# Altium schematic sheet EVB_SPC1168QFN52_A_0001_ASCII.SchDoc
size A3; 项目编号: SPSZ2023-052501A; 项目名称: 三相PFC-2.2KW压机+700W风机
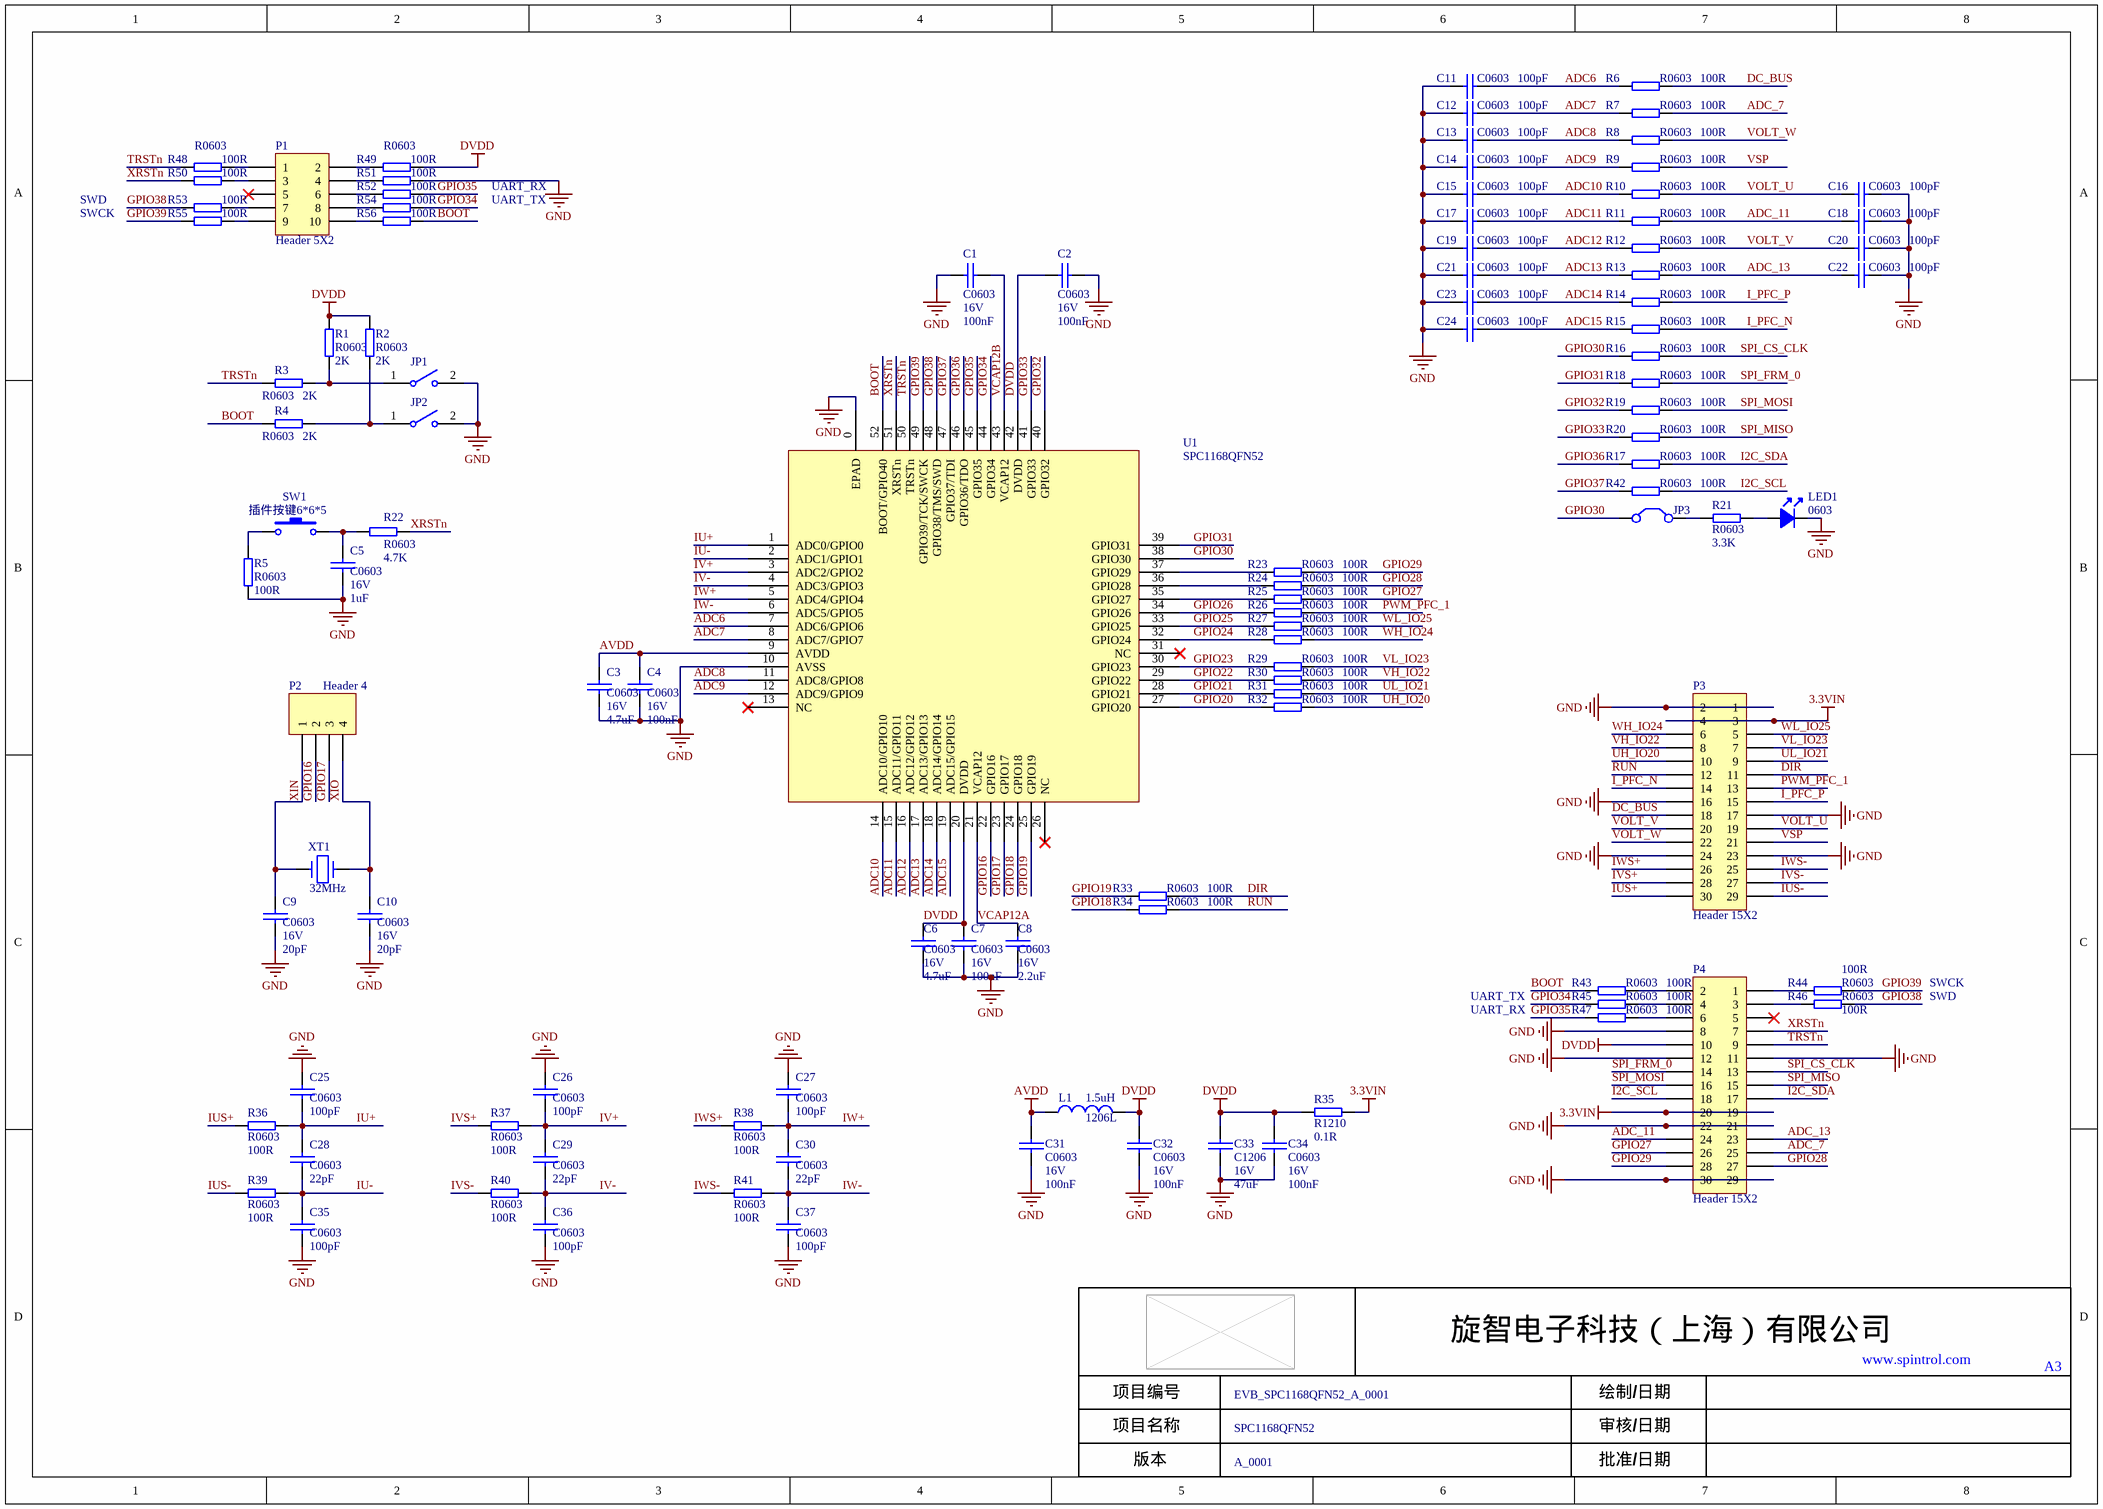
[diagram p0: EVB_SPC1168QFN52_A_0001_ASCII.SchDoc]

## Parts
C1  4.物料简述: C0603  3.物料描述（系统）: 16V  [0603C]  (hidden comment: 100nF)
C2  4.物料简述: C0603  3.物料描述（系统）: 16V  [0603C]  (hidden comment: 100nF)
C3  4.物料简述: C0603  3.物料描述（系统）: 16V  [0603C]  (hidden comment: 4.7uF)
C4  4.物料简述: C0603  3.物料描述（系统）: 16V  [0603C]  (hidden comment: 100nF)
C5  4.物料简述: C0603  3.物料描述（系统）: 16V  [0603C]  (hidden comment: 1uF)
C6  4.物料简述: C0603  3.物料描述（系统）: 16V  [0603C]  (hidden comment: 4.7uF)
C7  4.物料简述: C0603  3.物料描述（系统）: 16V  [0603C]  (hidden comment: 100nF)
C8  4.物料简述: C0603  3.物料描述（系统）: 16V  [0603C]  (hidden comment: 2.2uF)
C9  4.物料简述: C0603  3.物料描述（系统）: 16V  [0603C]  (hidden comment: 20pF)
C10  4.物料简述: C0603  3.物料描述（系统）: 16V  [0603C]  (hidden comment: 20pF)
C11  4.物料简述: C0603  [0603C]  (hidden comment: 100pF)
C12  4.物料简述: C0603  [0603C]  (hidden comment: 100pF)
C13  4.物料简述: C0603  [0603C]  (hidden comment: 100pF)
C14  4.物料简述: C0603  [0603C]  (hidden comment: 100pF)
C15  4.物料简述: C0603  [0603C]  (hidden comment: 100pF)
C16  4.物料简述: C0603  [0603C]  (hidden comment: 100pF)
C17  4.物料简述: C0603  [0603C]  (hidden comment: 100pF)
C18  4.物料简述: C0603  [0603C]  (hidden comment: 100pF)
C19  4.物料简述: C0603  [0603C]  (hidden comment: 100pF)
C20  4.物料简述: C0603  [0603C]  (hidden comment: 100pF)
C21  4.物料简述: C0603  [0603C]  (hidden comment: 100pF)
C22  4.物料简述: C0603  [0603C]  (hidden comment: 100pF)
C23  4.物料简述: C0603  [0603C]  (hidden comment: 100pF)
C24  4.物料简述: C0603  [0603C]  (hidden comment: 100pF)
C25  4.物料简述: C0603  [0603C]  (hidden comment: 100pF)
C26  4.物料简述: C0603  [0603C]  (hidden comment: 100pF)
C27  4.物料简述: C0603  [0603C]  (hidden comment: 100pF)
C28  4.物料简述: C0603  [0603C]  (hidden comment: 22pF)
C29  4.物料简述: C0603  [0603C]  (hidden comment: 22pF)
C30  4.物料简述: C0603  [0603C]  (hidden comment: 22pF)
C31  4.物料简述: C0603  3.物料描述（系统）: 16V  [0603C]  (hidden comment: 100nF)
C32  4.物料简述: C0603  3.物料描述（系统）: 16V  [0603C]  (hidden comment: 100nF)
C33  4.物料简述: C1206  3.物料描述（系统）: 16V  [1206C]  (hidden comment: 47uF)
C34  4.物料简述: C0603  3.物料描述（系统）: 16V  [0603C]  (hidden comment: 100nF)
C35  4.物料简述: C0603  [0603C]  (hidden comment: 100pF)
C36  4.物料简述: C0603  [0603C]  (hidden comment: 100pF)
C37  4.物料简述: C0603  [0603C]  (hidden comment: 100pF)
JP1  DSIC01LH-P  [Switch_3.5*10.4]  (value not drawn)
JP2  DSIC01LH-P  [Switch_3.5*10.4]  (value not drawn)
JP3  Jumper  [HDR1X2]  (value not drawn)
L1  1.5uH  [1206L]
LED1  4.物料简述: 0603  [LED0603]
P1  Header 5X2  [HDR2X5]
P2  Header 4  [HDR1X4]
P3  Header 15X2  [HDR2X15]
P4  Header 15X2  [HDR2X15]
R1  4.物料简述: R0603  [0603R]  (hidden comment: 2K)
R2  4.物料简述: R0603  [0603R]  (hidden comment: 2K)
R3  4.物料简述: R0603  [0603R]  (hidden comment: 2K)
R4  4.物料简述: R0603  [0603R]  (hidden comment: 2K)
R5  4.物料简述: R0603  [0603R]  (hidden comment: 100R)
R6  4.物料简述: R0603  [0603R]  (hidden comment: 100R)
R7  4.物料简述: R0603  [0603R]  (hidden comment: 100R)
R8  4.物料简述: R0603  [0603R]  (hidden comment: 100R)
R9  4.物料简述: R0603  [0603R]  (hidden comment: 100R)
R10  4.物料简述: R0603  [0603R]  (hidden comment: 100R)
R11  4.物料简述: R0603  [0603R]  (hidden comment: 100R)
R12  4.物料简述: R0603  [0603R]  (hidden comment: 100R)
R13  4.物料简述: R0603  [0603R]  (hidden comment: 100R)
R14  4.物料简述: R0603  [0603R]  (hidden comment: 100R)
R15  4.物料简述: R0603  [0603R]  (hidden comment: 100R)
R16  4.物料简述: R0603  [0603R]  (hidden comment: 100R)
R17  4.物料简述: R0603  [0603R]  (hidden comment: 100R)
R18  4.物料简述: R0603  [0603R]  (hidden comment: 100R)
R19  4.物料简述: R0603  [0603R]  (hidden comment: 100R)
R20  4.物料简述: R0603  [0603R]  (hidden comment: 100R)
R21  4.物料简述: R0603  [0603R]  (hidden comment: 3.3K)
R22  4.物料简述: R0603  [0603R]  (hidden comment: 4.7K)
R23  4.物料简述: R0603  [0603R]  (hidden comment: 100R)
R24  4.物料简述: R0603  [0603R]  (hidden comment: 100R)
R25  4.物料简述: R0603  [0603R]  (hidden comment: 100R)
R26  4.物料简述: R0603  [0603R]  (hidden comment: 100R)
R27  4.物料简述: R0603  [0603R]  (hidden comment: 100R)
R28  4.物料简述: R0603  [0603R]  (hidden comment: 100R)
R29  4.物料简述: R0603  [0603R]  (hidden comment: 100R)
R30  4.物料简述: R0603  [0603R]  (hidden comment: 100R)
R31  4.物料简述: R0603  [0603R]  (hidden comment: 100R)
R32  4.物料简述: R0603  [0603R]  (hidden comment: 100R)
R33  4.物料简述: R0603  [0603R]  (hidden comment: 100R)
R34  4.物料简述: R0603  [0603R]  (hidden comment: 100R)
R35  4.物料简述: R1210  [1210R]  (hidden comment: 0.1R)
R36  4.物料简述: R0603  [0603R]  (hidden comment: 100R)
R37  4.物料简述: R0603  [0603R]  (hidden comment: 100R)
R38  4.物料简述: R0603  [0603R]  (hidden comment: 100R)
R39  4.物料简述: R0603  [0603R]  (hidden comment: 100R)
R40  4.物料简述: R0603  [0603R]  (hidden comment: 100R)
R41  4.物料简述: R0603  [0603R]  (hidden comment: 100R)
R42  4.物料简述: R0603  [0603R]  (hidden comment: 100R)
R43  4.物料简述: R0603  [0603R]  (hidden comment: 100R)
R44  4.物料简述: R0603  [0603R]  (hidden comment: 100R)
R45  4.物料简述: R0603  [0603R]  (hidden comment: 100R)
R46  4.物料简述: R0603  [0603R]  (hidden comment: 100R)
R47  4.物料简述: R0603  [0603R]  (hidden comment: 100R)
R48  4.物料简述: R0603  [0603R]  (hidden comment: 100R)
R49  4.物料简述: R0603  [0603R]  (hidden comment: 100R)
R50  100R  [0603R]
R51  100R  [0603R]
R52  100R  [0603R]
R53  100R  [0603R]
R54  100R  [0603R]
R55  100R  [0603R]
R56  100R  [0603R]
SW1  插件按键6*6*5  [Key_6*6]
U1  SPC1168QFN52  [QFN-52-0.4]
XT1  32MHz  [XT-HI]

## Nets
3.3VIN: P3.3 P3.4 P4.19 P4.20 R35.2
AVDD: C3.2 C4.2 C31.2 L1.1 U1.9(AVDD)
DVDD: C2.2 C6.2 C7.2 C32.2 C33.2 C34.2 L1.2 P4.10 R1.1 R2.1 R35.1 R49.2 U1.20(DVDD) U1.42(DVDD)
GND: C1.1 C2.1 C3.1 C4.1 C5.1 C6.1 C7.1 C8.1 C9.1 C10.1 C11.2 C12.2 C13.2 C14.2 C15.2 C16.1 C17.2 C18.1 C19.2 C20.1 C21.2 C22.1 C23.2 C24.2 C25.2 C26.2 C27.2 C31.1 C32.1 C33.1 C34.1 C35.1 C36.1 C37.1 JP1.2 JP2.2 LED1.K P3.1 P3.2 P3.16 P3.17 P3.23 P3.24 P4.8 P4.11 P4.12 P4.21 P4.22 P4.29 P4.30 R5.2 R51.2 U1.0(EPAD) U1.10(AVSS)
ADC6: C11.1 R6.1 U1.7(ADC6/GPIO6)
ADC7: C12.1 R7.1 U1.8(ADC7/GPIO7)
ADC8: C13.1 R8.1 U1.11(ADC8/GPIO8)
ADC9: C14.1 R9.1 U1.12(ADC9/GPIO9)
ADC10: C15.1 R10.1 U1.14(ADC10/GPIO10)
ADC11: C17.1 R11.1 U1.15(ADC11/GPIO11)
ADC12: C19.1 R12.1 U1.16(ADC12/GPIO12)
ADC13: C21.1 R13.1 U1.17(ADC13/GPIO13)
ADC14: C23.1 R14.1 U1.18(ADC14/GPIO14)
ADC15: C24.1 R15.1 U1.19(ADC15/GPIO15)
ADC_7: P4.25 R7.2
ADC_11: C18.2 P4.24 R11.2
ADC_13: C22.2 P4.23 R13.2
BOOT: R4.2 R43.1 R56.2 U1.52(BOOT/GPIO40)
DC_BUS: P3.18 R6.2
DIR: P3.11 R33.2
GPIO16: P2.2 U1.22(GPIO16)
GPIO17: P2.3 U1.23(GPIO17)
GPIO18: R34.1 U1.24(GPIO18)
GPIO19: R33.1 U1.25(GPIO19)
GPIO20: R32.1 U1.27(GPIO20)
GPIO21: R31.1 U1.28(GPIO21)
GPIO22: R30.1 U1.29(GPIO22)
GPIO23: R29.1 U1.30(GPIO23)
GPIO24: R28.1 U1.32(GPIO24)
GPIO25: R27.1 U1.33(GPIO25)
GPIO26: R26.1 U1.34(GPIO26)
GPIO27: P4.26 R25.2
GPIO28: P4.27 R24.2
GPIO29: P4.28 R23.2
GPIO30: JP3.2(C2) R16.1 U1.38(GPIO30)
GPIO31: R18.1 U1.39(GPIO31)
GPIO32: R19.1 U1.40(GPIO32)
GPIO33: R20.1 U1.41(GPIO33)
GPIO34: R45.1 R54.2 U1.44(GPIO34)
GPIO35: R47.1 R52.2 U1.45(GPIO35)
GPIO36: R17.1 U1.46(GPIO36/TDO)
GPIO37: R42.1 U1.47(GPIO37/TDI)
GPIO38: R46.2 R53.1 U1.48(GPIO38/TMS/SWD)
GPIO39: R44.2 R55.1 U1.49(GPIO39/TCK/SWCK)
I2C_SCL: P4.18 R42.2
I2C_SDA: P4.17 R17.2
I_PFC_N: P3.14 R15.2
I_PFC_P: P3.15 R14.2
IU+: C25.1 C28.2 R36.2 U1.1(ADC0/GPIO0)
IU-: C28.1 C35.2 R39.2 U1.2(ADC1/GPIO1)
IUS+: P3.30 R36.1
IUS-: P3.29 R39.1
IV+: C26.1 C29.2 R37.2 U1.3(ADC2/GPIO2)
IV-: C29.1 C36.2 R40.2 U1.4(ADC3/GPIO3)
IVS+: P3.28 R37.1
IVS-: P3.27 R40.1
IW+: C27.1 C30.2 R38.2 U1.5(ADC4/GPIO4)
IW-: C30.1 C37.2 R41.2 U1.6(ADC5/GPIO5)
IWS+: P3.26 R38.1
IWS-: P3.25 R41.1
PWM_PFC_1: P3.13 R26.2
RUN: P3.12 R34.2
SPI_CS_CLK: P4.13 R16.2
SPI_FRM_0: P4.14 R18.2
SPI_MISO: P4.15 R20.2
SPI_MOSI: P4.16 R19.2
TRSTn: P4.9 R3.2 R48.1 U1.50(TRSTn)
UH_IO20: P3.10 R32.2
UL_IO21: P3.9 R31.2
VCAP12A: C8.2 U1.21(VCAP12)
VCAP12B: C1.2 U1.43(VCAP12)
VH_IO22: P3.8 R30.2
VL_IO23: P3.7 R29.2
VOLT_U: C16.2 P3.19 R10.2
VOLT_V: C20.2 P3.20 R12.2
VOLT_W: P3.22 R8.2
VSP: P3.21 R9.2
WH_IO24: P3.6 R28.2
WL_IO25: P3.5 R27.2
XIN: C9.2 P2.1 XT1.1
XIO: C10.2 P2.4 XT1.2
XRSTn: P4.7 R22.2 R50.1 U1.51(XRSTn)
NetC5_2: C5.2 R22.1 SW1.1
NetJP1_1: JP1.1 R1.2 R3.1
NetJP2_1: JP2.1 R2.2 R4.1
NetJP3_1: JP3.1(C1) R21.1
NetLED1_A: LED1.A R21.2
NetP1_1: P1.1 R48.2
NetP1_2: P1.2 R49.1
NetP1_3: P1.3 R50.2
NetP1_4: P1.4 R51.1
NetP1_6: P1.6 R52.1
NetP1_7: P1.7 R53.2
NetP1_8: P1.8 R54.1
NetP1_9: P1.9 R55.2
NetP1_10: P1.10 R56.1
NetP4_1: P4.1 R44.1
NetP4_2: P4.2 R43.2
NetP4_3: P4.3 R46.1
NetP4_4: P4.4 R45.2
NetP4_6: P4.6 R47.2
NetR5_1: R5.1 SW1.2
NetR23_1: R23.1 U1.37(GPIO29)
NetR24_1: R24.1 U1.36(GPIO28)
NetR25_1: R25.1 U1.35(GPIO27)

Not connected (* = marked no-connect by the designer): P1 5*; P4 5*; U1 13(NC)* 26(NC)* 31(NC)*

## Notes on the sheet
- SWD
- SWCK
- UART_RX
- UART_TX
- EVB_SPC1168QFN52_A_0001
- SPC1168QFN52
- A_0001

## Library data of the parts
C1-C37 = Capacitor: 无极性电容
JP1 JP2 = SW-2
JP3 = Jumper: Jumper Wire
L1 = Magnetic Beads: 磁珠
LED1 = LED: 发光二极管
P1 = Header 5X2: Header, 5-Pin, Dual row
P2 = Header 4: Header, 4-Pin
P3 P4 = Header 15X2: Header, 15-Pin, Dual row
R1-R56 = Resistance: 电阻
SW1 = SW-PB: Switch
XT1 = CRYSTAL-2P: 4.物料简述: C295082; 3.物料描述（系统）: XIHCELNANF-32MHZ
